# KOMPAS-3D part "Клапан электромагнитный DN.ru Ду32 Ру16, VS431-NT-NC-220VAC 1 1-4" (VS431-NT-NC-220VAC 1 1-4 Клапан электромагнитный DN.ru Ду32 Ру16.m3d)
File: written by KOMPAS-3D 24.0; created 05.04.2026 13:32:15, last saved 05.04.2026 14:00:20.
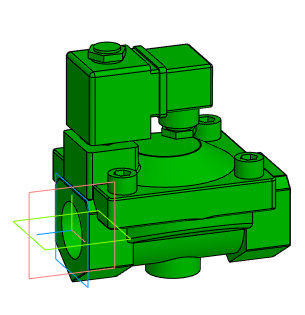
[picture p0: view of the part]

Document properties: Автор: artio; Полное имя файла: C:\Users\artio\OneDrive\Рабочий стол\Клапан электромагнитный DN.ru\VS431\VS431-NT-NC\VS431-NT-NC-220VAC\Ду32\VS431-NT-NC-220VAC 1 1-4 Клапан электромагнитный DN.ru Ду32 Ру16.m3d

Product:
- Body: Тело 1  | qty 1
    Масса: 3.709873
- Part/product: Клапан электромагнитный DN.ru Ду32 Ру16  | designation VS431-NT-NC-220VAC 1 1-4
    Масса: 1.701
    Раздел спецификации: Прочие изделия
    Примечание: D130-04671
    additional columns: ef56311e-7521-43dc-8291-0e6108b3d81d; artio; c; Шероховатость не задана; Да

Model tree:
1. Операция без истории:1

Expressions: VS431-NT-NC-220VAC 1 1-4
